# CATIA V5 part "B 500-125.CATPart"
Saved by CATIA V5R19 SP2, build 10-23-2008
Part number: B 500-125
Bounding box of the stored display mesh (mm): x -18.951 to 18.951, y -18.952 to 18.952, z 0 to 300
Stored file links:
  C:\Users\Bora\Desktop\3D Katı model\B serisi\B 500\B 500-125.CATPart
  C:\Program Files\Dassault Systemes\B19\intel_a\reffiles\standard\MetricThickPitch.txt
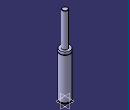
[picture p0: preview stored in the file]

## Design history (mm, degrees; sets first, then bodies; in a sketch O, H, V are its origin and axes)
Body1 (main body)
  Sketch1 on yz-plane, origin (0, 0, 0), H (0, 1, 0), V (0, 0, 1)
    point P1 (19, 163.5)
    point P4 (19, 161.5)
    point P7 (19, 163.5)
    point P8 (19, 161.5)
    point P9 (10, 299)
    point P11 (10, 299)
    line L1 (19, 163.5) -> (19, 173)
    line L2 (19, 7.5) -> (19, 161.5)
    line L3 (16.5, 7.5) -> (16.5, 4)
    arc A1 centre (19, 162.5) radius 1 from (19, 163.5) to (19, 161.5) ccw
    arc A2 centre (9, 299) radius 1 from (10, 299) to (9, 300) ccw
    line L4 (10, 299) -> (10, 173)
    line L5 (19, 0) -> (19, 4)
    line L6 (9, 300) -> (0, 300)
    point P15 (0, 300)
    line L7 (10, 173) -> (19, 173)
    line L8 (0, 0) -> (19, 0)
    line L9 (16.5, 7.5) -> (19, 7.5)
    line L10 (16.5, 4) -> (19, 4)
    coincidence: P15 V, P1 P7, P4 P8, P9 P11
    tangency: L6 A2
    horizontal: L7 H, L8 H, L9 H, L10 H
  Shaft1: profile Sketch1, axis Sketch1.V, angle 360
  Sketch2 on face of Shaft1 from Sketch1.L8, origin (0, 0, 0), H (1, 0, 0), V (0, -1, 0)
    point P1 (0, 0)
  Hole1: placed by Sketch2, at (0, 0, 0) direction (0, 0, 1), diameter 6.647, depth 7, threaded "M8", thread diameter 8, thread depth 7, pitch 1.25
